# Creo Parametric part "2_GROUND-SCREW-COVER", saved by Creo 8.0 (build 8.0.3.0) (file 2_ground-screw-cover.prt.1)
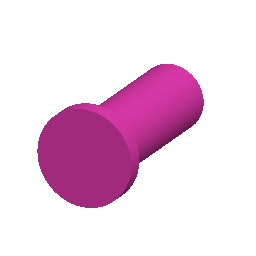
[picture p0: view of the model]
Units: millimeter Newton Second (mmNs); MM, TONNE, SECS

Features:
  1. datum plane "DTM1"
  2. protrusion
  3. datum plane "DTM2"
  4. protrusion
  5. datum plane "DTM3"
  6. cut

Layers: 0_ALL_AXIS, 0_ALL_CSYS, 0_ALL_CURVES, 0_ALL_PLANES, 0_ALL_POINTS, 0_ALL_SURFS, GROUND-SCREW-COVER

Surfaces: 4 plane, 3 cylinder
